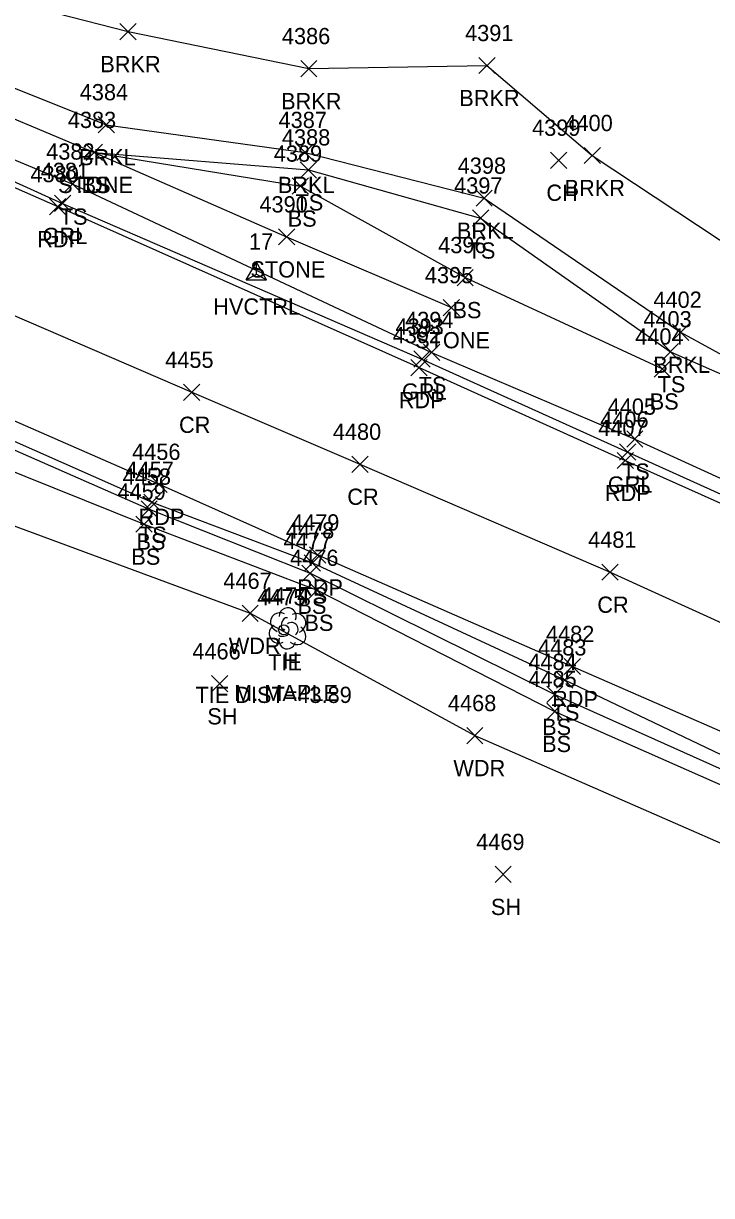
# Model space of a CAD drawing. Extents: x 1611797 to 1633212, y 298978 to 305475.
# Drawn here: x 1619390.4 to 1619475.1, y 301380.5 to 301524.7 of the extents above; entities that cross this region are included whole.
import ezdxf

# ---------------------------------------------------------------- set-up
doc = ezdxf.new("R2010")
doc.units = 0
for name, color, linetype in [('C_A', 7, 'Continuous'), ('C_C', 7, 'Continuous'), ('C_I', 7, 'Continuous'), ('CBP', 7, 'Continuous'), ('CPSM', 7, 'Continuous'), ('L_A', 7, 'Continuous'), ('L_C', 7, 'Continuous'), ('L_I', 7, 'Continuous'), ('L_TIC', 7, 'Continuous'), ('LASF', 7, 'Continuous'), ('LAWA', 7, 'Continuous'), ('LAWE', 7, 'Continuous'), ('LELB', 7, 'Continuous'), ('LTD', 7, 'Continuous'), ('P_A', 7, 'Continuous'), ('P_I', 7, 'Continuous'), ('P_TIC', 7, 'Continuous'), ('PET', 7, 'Continuous'), ('PRC', 7, 'Continuous'), ('R_A', 7, 'Continuous'), ('R_I', 7, 'Continuous'), ('R_TIC', 7, 'Continuous'), ('RGR', 7, 'Continuous')]:
    doc.layers.add(name, color=color, linetype=linetype)

msp = doc.modelspace()

# ---------------------------------------------------------------- linework, layer by layer
at = {"layer": 'CBP'}
for radius in [0.625, 0.0833]:
    msp.add_circle((1619422.43, 301450.09), radius, dxfattribs=at)
at = {"layer": 'CPSM'}
for p, q in [((1619417.81, 301493.14), (1619419.06, 301495.31)), ((1619420.31, 301493.14), (1619419.06, 301495.31)), ((1619419.06, 301493.86), (1619419.06, 301495.31)), ((1619417.81, 301493.14), (1619419.06, 301493.86)), ((1619417.81, 301493.14), (1619420.31, 301493.14)), ((1619419.06, 301493.86), (1619419.06, 301493.86)), ((1619419.06, 301493.86), (1619420.31, 301493.14))]:
    msp.add_line(p, q, dxfattribs=at)
at = {"layer": 'L_TIC'}
for points in [[(1619402.26, 301522.68), (1619404.26, 301524.68)], [(1619404.26, 301522.68), (1619402.26, 301524.68)], [(1619446.45, 301518.51), (1619448.45, 301520.51)], [(1619448.45, 301518.51), (1619446.45, 301520.51)], [(1619424.52, 301518.13), (1619426.52, 301520.13)], [(1619426.52, 301518.13), (1619424.52, 301520.13)], [(1619399.58, 301511.23), (1619401.58, 301513.23)], [(1619401.58, 301511.23), (1619399.58, 301513.23)], [(1619398.11, 301507.82), (1619400.11, 301509.82)], [(1619400.11, 301507.82), (1619398.11, 301509.82)], [(1619398.11, 301507.82), (1619400.11, 301509.82)], [(1619400.11, 301507.82), (1619398.11, 301509.82)], [(1619398.11, 301507.82), (1619400.11, 301509.82)], [(1619400.11, 301507.82), (1619398.11, 301509.82)], [(1619424.06, 301507.82), (1619426.06, 301509.82)], [(1619426.06, 301507.82), (1619424.06, 301509.82)], [(1619455.28, 301506.86), (1619457.28, 301508.86)], [(1619457.28, 301506.86), (1619455.28, 301508.86)], [(1619459.42, 301507.44), (1619461.42, 301509.44)], [(1619461.42, 301507.44), (1619459.42, 301509.44)], [(1619424.47, 301505.67), (1619426.47, 301507.67)], [(1619426.47, 301505.67), (1619424.47, 301507.67)], [(1619395.45, 301503.93), (1619397.45, 301505.93)], [(1619397.45, 301503.93), (1619395.45, 301505.93)], [(1619423.48, 301503.68), (1619425.48, 301505.68)], [(1619425.48, 301503.68), (1619423.48, 301505.68)], [(1619446.11, 301502.19), (1619448.11, 301504.19)], [(1619448.11, 301502.19), (1619446.11, 301504.19)], [(1619445.67, 301499.75), (1619447.67, 301501.75)], [(1619447.67, 301499.75), (1619445.67, 301501.75)], [(1619421.78, 301497.43), (1619423.78, 301499.43)], [(1619423.78, 301497.43), (1619421.78, 301499.43)], [(1619443.77, 301492.42), (1619445.77, 301494.42)], [(1619445.77, 301492.42), (1619443.77, 301494.42)], [(1619442.07, 301488.72), (1619444.07, 301490.72)], [(1619444.07, 301488.72), (1619442.07, 301490.72)], [(1619470.29, 301485.7), (1619472.29, 301487.7)], [(1619472.29, 301485.7), (1619470.29, 301487.7)], [(1619439.64, 301483.21), (1619441.64, 301485.21)], [(1619441.64, 301483.21), (1619439.64, 301485.21)], [(1619469.05, 301483.3), (1619471.05, 301485.3)], [(1619471.05, 301483.3), (1619469.05, 301485.3)], [(1619468.05, 301481.18), (1619470.05, 301483.18)], [(1619470.05, 301481.18), (1619468.05, 301483.18)], [(1619464.66, 301472.55), (1619466.66, 301474.55)], [(1619466.66, 301472.55), (1619464.66, 301474.55)], [(1619404.86, 301463.94), (1619406.86, 301465.94)], [(1619406.86, 301463.94), (1619404.86, 301465.94)], [(1619405.21, 301464.78), (1619407.21, 301466.78)], [(1619407.21, 301464.78), (1619405.21, 301466.78)], [(1619404.23, 301462.09), (1619406.23, 301464.09)], [(1619406.23, 301462.09), (1619404.23, 301464.09)], [(1619424.96, 301457.32), (1619426.96, 301459.32)], [(1619426.96, 301457.32), (1619424.96, 301459.32)], [(1619424.68, 301456.05), (1619426.68, 301458.05)], [(1619426.68, 301456.05), (1619424.68, 301458.05)], [(1619425.54, 301453.95), (1619427.54, 301455.95)], [(1619427.54, 301453.95), (1619425.54, 301455.95)], [(1619417.3, 301451.12), (1619419.3, 301453.12)], [(1619419.3, 301451.12), (1619417.3, 301453.12)], [(1619413.55, 301442.45), (1619415.55, 301444.45)], [(1619415.55, 301442.45), (1619413.55, 301444.45)], [(1619456.01, 301442.93), (1619458.01, 301444.93)], [(1619458.01, 301442.93), (1619456.01, 301444.93)], [(1619454.81, 301441.15), (1619456.81, 301443.15)], [(1619456.81, 301441.15), (1619454.81, 301443.15)], [(1619454.81, 301439.05), (1619456.81, 301441.05)], [(1619456.81, 301439.05), (1619454.81, 301441.05)], [(1619444.96, 301436.08), (1619446.96, 301438.08)], [(1619446.96, 301436.08), (1619444.96, 301438.08)], [(1619448.45, 301419), (1619450.45, 301421)], [(1619450.45, 301419), (1619448.45, 301421)]]:
    msp.add_lwpolyline(points, dxfattribs=at)
at = {"layer": 'LASF'}
msp.add_lwpolyline([(1619399.11, 301508.82), (1619422.78, 301498.43), (1619443.07, 301489.72)], dxfattribs=at)
at = {"layer": 'LAWA'}
msp.add_lwpolyline([(1618882.81, 301567.28), (1618933.27, 301549.67), (1618966.13, 301547.74), (1618995.78, 301536.72), (1619030.89, 301531.11), (1619057.33, 301531.01), (1619095.91, 301526.5), (1619129.18, 301525.73), (1619150.8, 301525.95), (1619170.44, 301523.1), (1619199.54, 301523.39), (1619227.92, 301521), (1619255.54, 301516.31), (1619296.45, 301501.63), (1619335.16, 301482.98), (1619367.14, 301471.03), (1619418.3, 301452.12), (1619445.96, 301437.08), (1619483.46, 301420.7), (1619501.91, 301410.17), (1619499.78, 301408.21)], dxfattribs=at)
at = {"layer": 'LAWE'}
for points in [[(1619121.54, 301596.78), (1619127.27, 301586.98), (1619139.06, 301578.8), (1619159, 301574.34), (1619183.18, 301572.3), (1619208.56, 301571.29), (1619241.26, 301566.88), (1619274.96, 301559.5), (1619298.41, 301555.12), (1619318.82, 301545.34), (1619330.43, 301538.53), (1619346.68, 301531.42), (1619377.57, 301521.38), (1619400.58, 301512.23), (1619425.06, 301508.82), (1619447.11, 301503.19), (1619471.29, 301486.7), (1619494.67, 301473.93), (1619527.64, 301465.84), (1619544.48, 301462.53)], [(1619136.24, 301595.23), (1619140.25, 301584.78), (1619161.79, 301583.57), (1619186.78, 301582.21), (1619209.91, 301580.75), (1619246.07, 301579.22), (1619276.73, 301571.04), (1619324.15, 301554.68), (1619337.82, 301545.56), (1619347.88, 301539.03), (1619381.89, 301529.19), (1619403.26, 301523.68), (1619425.52, 301519.13), (1619447.45, 301519.51), (1619460.42, 301508.44), (1619478.58, 301496.43), (1619500.86, 301484.81), (1619530.24, 301476.17)]]:
    msp.add_lwpolyline(points, dxfattribs=at)
at = {"layer": 'LELB'}
for points in [[(1619317.17, 301538.73), (1619315.62, 301540.45), (1619317.24, 301543.31), (1619318.13, 301543.25), (1619329.45, 301536.19), (1619345.54, 301530.03), (1619376.2, 301519.31), (1619381.7, 301516.1), (1619399.11, 301508.82), (1619424.48, 301504.68), (1619444.77, 301493.42), (1619469.05, 301482.18)], [(1619257.04, 301523.11), (1619288.29, 301511.99), (1619300.15, 301507.59), (1619319.19, 301501.19), (1619349.47, 301488.14), (1619380.51, 301476.04), (1619405.86, 301464.94), (1619425.68, 301457.05), (1619455.81, 301442.15), (1619487.51, 301427.94), (1619510.2, 301416.95), (1619508.81, 301414.78)], [(1619261.97, 301519.13), (1619288.17, 301510.33), (1619300.24, 301505.96), (1619319.06, 301498.92), (1619348.87, 301486.68), (1619379.41, 301473.48), (1619405.23, 301463.09), (1619426.54, 301454.95), (1619455.81, 301440.05), (1619486.75, 301426.39), (1619508.81, 301414.78)], [(1619374.24, 301514.17), (1619396.45, 301504.93), (1619440.64, 301484.21), (1619465.66, 301473.55), (1619491.73, 301461.64), (1619517.36, 301453.25), (1619539.79, 301440.1), (1619561.74, 301430.67), (1619592.22, 301416.88), (1619623.08, 301401.62), (1619646.41, 301391.76), (1619666.94, 301385.23), (1619677.78, 301385.59), (1619685.14, 301386.73)], [(1619399.11, 301508.82), (1619425.47, 301506.67), (1619446.67, 301500.75), (1619470.05, 301484.3), (1619495.57, 301473.11), (1619526.9, 301463.14), (1619543.53, 301458.98)], [(1619350.31, 301489.81), (1619380.89, 301476.99), (1619406.21, 301465.78), (1619425.96, 301458.32), (1619457.01, 301443.93), (1619488.18, 301429.04), (1619515.79, 301415.84), (1619523.25, 301412.34), (1619557.22, 301396.43), (1619595.64, 301379.74), (1619625.49, 301366.11), (1619664.9, 301348.53), (1619700.1, 301332.19), (1619732.76, 301315.82), (1619759.48, 301302.13), (1619789.83, 301287.62), (1619820.2, 301275.83), (1619850.42, 301266.87), (1619878.56, 301257.32), (1619912.05, 301251.69), (1619947.78, 301244.54), (1619986.64, 301235.92)]]:
    msp.add_lwpolyline(points, dxfattribs=at)
at = {"layer": 'LTD'}
msp.add_line((1619422.88, 301450.32), (1619422.88, 301450.32), dxfattribs=at)
msp.add_line((1619422.88, 301450.32), (1619422.88, 301450.32), dxfattribs=at)
msp.add_arc((1619422.93, 301451.75), 1.05, 335.5272, 180.9563, dxfattribs=at)
for centre, major_axis, ratio, start_param, end_param in [((1619422.09, 301450.98), (1.21, -0.51), 0.895232, 1.570796, 4.712389), ((1619422.67, 301450.77), (-0.208, -0.792), 0.645439, 3.141593, 6.283185), ((1619423.38, 301450.15), (-0.5, 0.667), 0.989748, 3.141593, 6.283185), ((1619423.92, 301450.9), (-1.14, -0.48), 0.949671, 1.570796, 4.712389), ((1619421.8, 301449.61), (0.58, -1.04), 0.959034, 3.141593, 6.283185), ((1619422.42, 301449.57), (-0.625, -0.083), 0.423636, 0, 3.141593), ((1619423.88, 301449.48), (-1.09, 0.79), 0.841452, 1.570796, 4.712389), ((1619422.88, 301448.82), (0.26, 1.06), 0.942809, 1.570796, 4.712389)]:
    msp.add_ellipse(centre, major_axis=major_axis, ratio=ratio, start_param=start_param, end_param=end_param, dxfattribs=at)
at = {"layer": 'P_TIC'}
for points in [[(1619393.6, 301501.15), (1619395.6, 301503.15)], [(1619395.6, 301501.15), (1619393.6, 301503.15)], [(1619438.1, 301481.35), (1619440.1, 301483.35)], [(1619440.1, 301481.35), (1619438.1, 301483.35)], [(1619410.1, 301478.31), (1619412.1, 301480.31)], [(1619412.1, 301478.31), (1619410.1, 301480.31)], [(1619430.82, 301469.46), (1619432.82, 301471.46)], [(1619432.82, 301469.46), (1619430.82, 301471.46)], [(1619463.49, 301469.92), (1619465.49, 301471.92)], [(1619465.49, 301469.92), (1619463.49, 301471.92)], [(1619406.08, 301466.99), (1619408.08, 301468.99)], [(1619408.08, 301466.99), (1619406.08, 301468.99)], [(1619425.6, 301458.3), (1619427.6, 301460.3)], [(1619427.6, 301458.3), (1619425.6, 301460.3)], [(1619461.61, 301456.18), (1619463.61, 301458.18)], [(1619463.61, 301456.18), (1619461.61, 301458.18)], [(1619456.98, 301444.58), (1619458.98, 301446.58)], [(1619458.98, 301444.58), (1619456.98, 301446.58)]]:
    msp.add_lwpolyline(points, dxfattribs=at)
at = {"layer": 'PET'}
for points in [[(1618888.23, 301580.37), (1618933.16, 301570.89), (1618970.31, 301563.97), (1618999.63, 301559.01), (1619034.35, 301554.34), (1619061.55, 301550.65), (1619097.22, 301547.2), (1619129.9, 301544.44), (1619159.56, 301541.04), (1619184.98, 301537.63), (1619217.73, 301532.43), (1619257.09, 301523.65), (1619289.53, 301513.85), (1619319.75, 301503.72), (1619351.37, 301491.53), (1619381.67, 301479.11), (1619407.08, 301467.99), (1619426.6, 301459.3), (1619457.98, 301445.58), (1619489.4, 301431.89), (1619518.89, 301418.33), (1619525.23, 301415.46), (1619558.04, 301399.85), (1619596.27, 301382.3)], [(1619240.37, 301554.95), (1619274.06, 301546.88), (1619292.74, 301541.21), (1619313.19, 301534.69), (1619345.01, 301523.34), (1619373.79, 301511.3), (1619394.6, 301502.15), (1619439.1, 301482.35), (1619464.49, 301470.92), (1619491.36, 301458.9), (1619515.17, 301447.9), (1619539.87, 301436.67), (1619561.18, 301427.13), (1619589.22, 301414.46)]]:
    msp.add_lwpolyline(points, dxfattribs=at)
at = {"layer": 'PRC'}
msp.add_lwpolyline([(1618901.02, 301590.58), (1618940.05, 301582.59), (1618973.24, 301576.03), (1619000.99, 301571.61), (1619035.45, 301566.56), (1619061.58, 301563.28), (1619097.97, 301559.63), (1619131.37, 301556.26), (1619160.97, 301552.75), (1619186.04, 301549.32), (1619221.45, 301543.36), (1619260.73, 301534.56), (1619294.21, 301525.01), (1619322.54, 301515.15), (1619356.63, 301502.41), (1619386.84, 301489.79), (1619411.1, 301479.31), (1619431.82, 301470.46), (1619462.61, 301457.18), (1619493.8, 301442.98), (1619525.59, 301428.61), (1619540.79, 301421.69), (1619561.88, 301411.99), (1619599.81, 301394.69)], dxfattribs=at)
at = {"layer": 'R_TIC'}
for points in [[(1619394.21, 301501.55), (1619396.21, 301503.55)], [(1619396.21, 301501.55), (1619394.21, 301503.55)], [(1619438.45, 301482.4), (1619440.45, 301484.4)], [(1619440.45, 301482.4), (1619438.45, 301484.4)], [(1619463.79, 301470.96), (1619465.79, 301472.96)], [(1619465.79, 301470.96), (1619463.79, 301472.96)]]:
    msp.add_lwpolyline(points, dxfattribs=at)
at = {"layer": 'RGR'}
msp.add_lwpolyline([(1619113.04, 301582.5), (1619113.91, 301576.54), (1619116.84, 301573.48), (1619121.6, 301572.21), (1619138.62, 301570.86), (1619159.07, 301568.7), (1619183.38, 301565.96), (1619196, 301564), (1619207.6, 301562.14), (1619240.46, 301556.07), (1619274.51, 301547.73), (1619293.11, 301542.29), (1619313.83, 301535.74), (1619345.65, 301523.87), (1619374.43, 301511.91), (1619395.21, 301502.55), (1619439.45, 301483.4), (1619464.79, 301471.96), (1619490.69, 301460.24), (1619515.52, 301448.47), (1619540.39, 301438.03), (1619561.3, 301428.91), (1619589.96, 301416.04)], dxfattribs=at)

# ---------------------------------------------------------------- texts
at = {"layer": 'C_A'}
for s, p in [('HVCTRL', (1619413.75, 301488.86)), ('TIE', (1619420.51, 301445.09))]:
    msp.add_text(s, height=2, dxfattribs=at).set_placement(p)
at = {"layer": 'C_C'}
msp.add_text('TIE DIST=43.89', height=2, dxfattribs=at).set_placement((1619411.56, 301441.09))
at = {"layer": 'C_I'}
for s, p in [('17', (1619418.16, 301496.86)), ('4475', (1619419.17, 301453.09))]:
    msp.add_text(s, height=2, dxfattribs=at).set_placement(p)
at = {"layer": 'L_A'}
for s, p in [('BRKR', (1619399.85, 301518.68)), ('BRKR', (1619422.11, 301514.13)), ('BRKR', (1619444.04, 301514.51)), ('BRKL', (1619397.22, 301507.23)), ('STONE', (1619394.65, 301503.82)), ('TS', (1619397.51, 301503.82)), ('BS', (1619397.55, 301503.82)), ('BRKL', (1619421.71, 301503.82)), ('CH', (1619454.77, 301502.86)), ('BRKR', (1619457.01, 301503.44)), ('TS', (1619423.88, 301501.67)), ('TS', (1619394.86, 301499.93)), ('BS', (1619422.92, 301499.68)), ('BRKL', (1619443.75, 301498.19)), ('TS', (1619445.08, 301495.75)), ('STONE', (1619418.33, 301493.43)), ('BS', (1619443.21, 301488.42)), ('STONE', (1619438.61, 301484.72)), ('BRKL', (1619467.93, 301481.7)), ('TS', (1619439.05, 301479.21)), ('TS', (1619468.46, 301479.3)), ('BS', (1619467.49, 301477.18)), ('TS', (1619464.07, 301468.55)), ('TS', (1619404.61, 301460.78)), ('BS', (1619404.3, 301459.94)), ('BS', (1619403.67, 301458.09)), ('BS', (1619424.12, 301452.05)), ('TS', (1619424.37, 301453.32)), ('BS', (1619424.98, 301449.95)), ('WDR', (1619415.67, 301447.12)), ('H', (1619422.32, 301445.32)), ('SH', (1619413.03, 301438.45)), ('TS', (1619455.42, 301438.93)), ('BS', (1619454.25, 301437.15)), ('BS', (1619454.25, 301435.05)), ('WDR', (1619443.32, 301432.08)), ('SH', (1619447.94, 301415))]:
    msp.add_text(s, height=2, dxfattribs=at).set_placement(p)
at = {"layer": 'L_C'}
msp.add_text('M. MAPLE', height=2, dxfattribs=at).set_placement((1619416.33, 301441.32))
at = {"layer": 'L_I'}
for s, p in [('4386', (1619422.21, 301522.13)), ('4391', (1619444.76, 301522.51)), ('4384', (1619397.32, 301515.23)), ('4383', (1619395.85, 301511.82)), ('4383', (1619395.85, 301511.82)), ('4383', (1619395.85, 301511.82)), ('4387', (1619421.8, 301511.82)), ('4400', (1619456.99, 301511.44)), ('4388', (1619422.21, 301509.67)), ('4399', (1619453.01, 301510.86)), ('4382', (1619393.19, 301507.93)), ('4389', (1619421.21, 301507.68)), ('4398', (1619443.85, 301506.19)), ('4397', (1619443.41, 301503.75)), ('4390', (1619419.44, 301501.43)), ('4396', (1619441.45, 301496.42)), ('4395', (1619439.81, 301492.72)), ('4402', (1619467.95, 301489.7)), ('4394', (1619437.38, 301487.21)), ('4403', (1619466.71, 301487.3)), ('4404', (1619465.71, 301485.18)), ('4405', (1619462.32, 301476.55)), ('4458', (1619402.6, 301467.94)), ('4457', (1619402.95, 301468.78)), ('4459', (1619401.96, 301466.09)), ('4478', (1619422.7, 301461.32)), ('4477', (1619422.42, 301460.05)), ('4476', (1619423.22, 301457.95)), ('4467', (1619415, 301455.12)), ('4474', (1619419.62, 301453.32)), ('4466', (1619411.18, 301446.45)), ('4483', (1619453.75, 301446.93)), ('4484', (1619452.55, 301445.15)), ('4485', (1619452.55, 301443.05)), ('4468', (1619442.65, 301440.08)), ('4469', (1619446.13, 301423))]:
    msp.add_text(s, height=2, dxfattribs=at).set_placement(p)
at = {"layer": 'P_A'}
for s, p in [('RDP', (1619392.08, 301497.15)), ('RDP', (1619436.59, 301477.35)), ('CR', (1619409.54, 301474.31)), ('CR', (1619430.26, 301465.46)), ('RDP', (1619461.98, 301465.92)), ('RDP', (1619404.57, 301462.99)), ('RDP', (1619424.08, 301454.3)), ('CR', (1619461.04, 301452.18)), ('RDP', (1619455.47, 301440.58))]:
    msp.add_text(s, height=2, dxfattribs=at).set_placement(p)
at = {"layer": 'P_I'}
for s, p in [('4380', (1619391.25, 301505.15)), ('4392', (1619435.85, 301485.35)), ('4455', (1619407.84, 301482.31)), ('4407', (1619461.15, 301473.92)), ('4480', (1619428.48, 301473.46)), ('4456', (1619403.77, 301470.99)), ('4479', (1619423.33, 301462.3)), ('4481', (1619459.91, 301460.18)), ('4482', (1619454.72, 301448.58))]:
    msp.add_text(s, height=2, dxfattribs=at).set_placement(p)
at = {"layer": 'R_A'}
for p in [(1619392.75, 301497.55), (1619436.99, 301478.4), (1619462.33, 301466.96)]:
    msp.add_text('GRL', height=2, dxfattribs=at).set_placement(p)
at = {"layer": 'R_I'}
for s, p in [('4381', (1619392.52, 301505.55)), ('4393', (1619436.19, 301486.4)), ('4406', (1619461.4, 301474.96))]:
    msp.add_text(s, height=2, dxfattribs=at).set_placement(p)

doc.saveas('drawing.dxf')
